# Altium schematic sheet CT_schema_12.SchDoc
size 274 x 160 mm
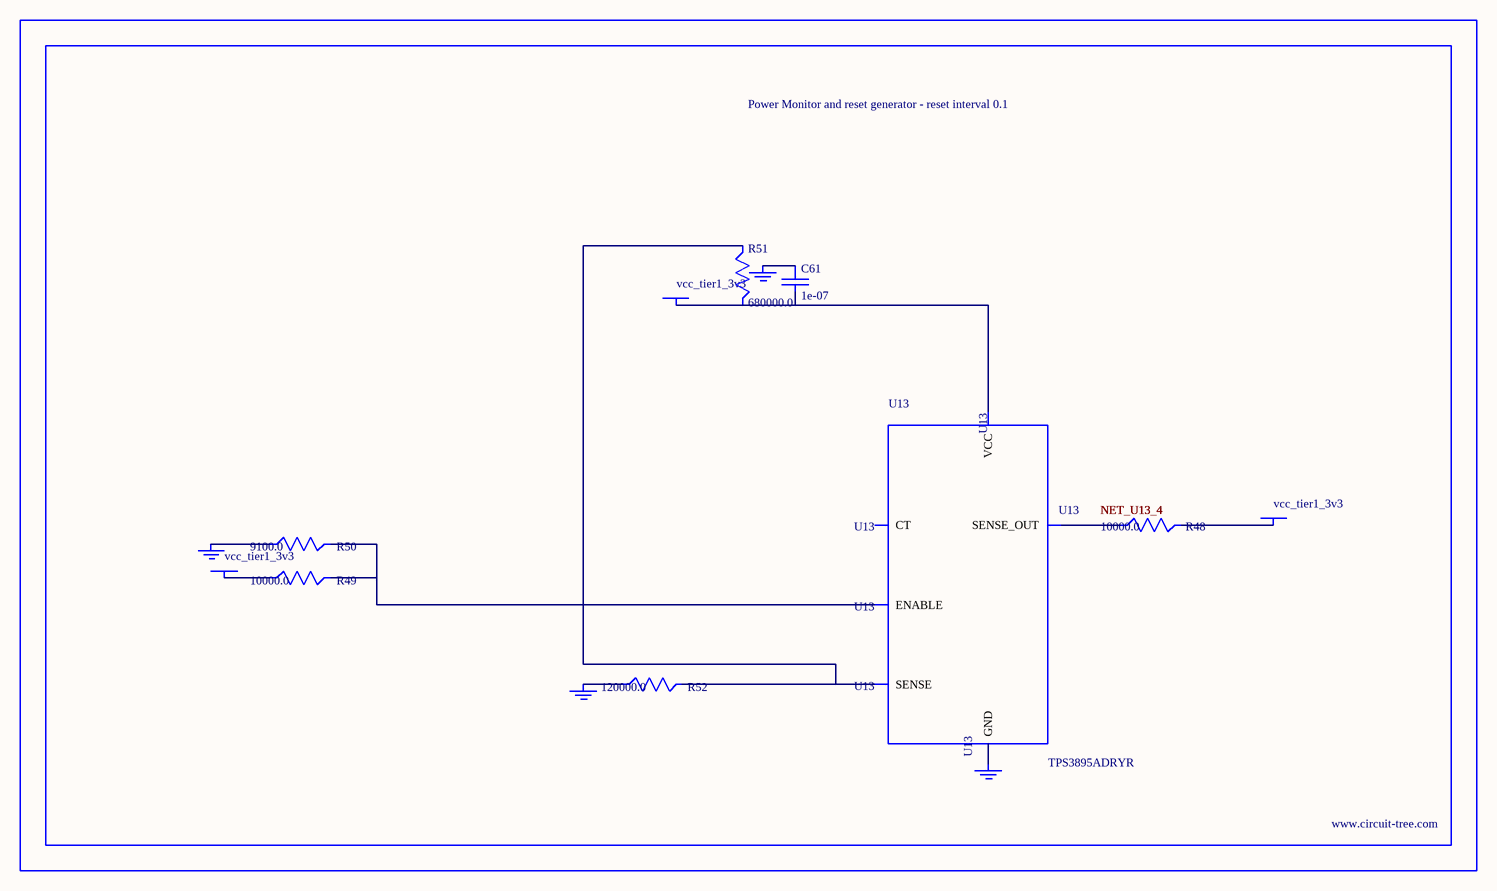
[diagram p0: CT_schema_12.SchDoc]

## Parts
BORDER11  (no value)
C61  1e-07  [C0402]
GND_INSTANCE_11_0  (no value)
GND_INSTANCE_11_1  (no value)
GND_INSTANCE_11_2  (no value)
GND_INSTANCE_11_3  (no value)
POWER_INSTANCE_11_0  vcc_tier1_3v3
POWER_INSTANCE_11_1  vcc_tier1_3v3
POWER_INSTANCE_11_2  vcc_tier1_3v3
R48  10000.0  [R0603]
R49  10000.0  [R0603]
R50  9100.0  [R0603]
R51  680000.0  [R0603]
R52  120000.0  [R0603]
U13  TPS3895ADRYR  [SON-6]

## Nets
NetC61_1: C61.1 GND_INSTANCE_11_2.0(GND)
NetC61_2: C61.2 POWER_INSTANCE_11_2.0(PWR) R51.2 U13.6(VCC)
NetGND_INSTANCE_11_0_0: GND_INSTANCE_11_0.0(GND) R50.1
NetGND_INSTANCE_11_1_0: GND_INSTANCE_11_1.0(GND) R52.1
NetGND_INSTANCE_11_3_0: GND_INSTANCE_11_3.0(GND) U13.2(GND)
NetPOWER_INSTANCE_11_0_0: POWER_INSTANCE_11_0.0(PWR) R49.1
NetPOWER_INSTANCE_11_1_0: POWER_INSTANCE_11_1.0(PWR) R48.2
NetR48_1: R48.1 U13.4(SENSE_OUT)
NetR49_2: R49.2 R50.2 U13.1(ENABLE)
NetR51_1: R51.1 R52.2 U13.3(SENSE)

Not connected (* = marked no-connect by the designer): U13 5(CT)

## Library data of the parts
BORDER11 = BORDER_PAGE11
C61 = C0402C104K3RACTU
GND_INSTANCE_11_0-GND_INSTANCE_11_3 = GND
POWER_INSTANCE_11_0-POWER_INSTANCE_11_2 = PWR
R48 R49 = RC0603JR-0710KL
R50 = RC0603JR-079K1L
R51 = RC0603JR-07680KL
R52 = RC0603JR-07120KL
